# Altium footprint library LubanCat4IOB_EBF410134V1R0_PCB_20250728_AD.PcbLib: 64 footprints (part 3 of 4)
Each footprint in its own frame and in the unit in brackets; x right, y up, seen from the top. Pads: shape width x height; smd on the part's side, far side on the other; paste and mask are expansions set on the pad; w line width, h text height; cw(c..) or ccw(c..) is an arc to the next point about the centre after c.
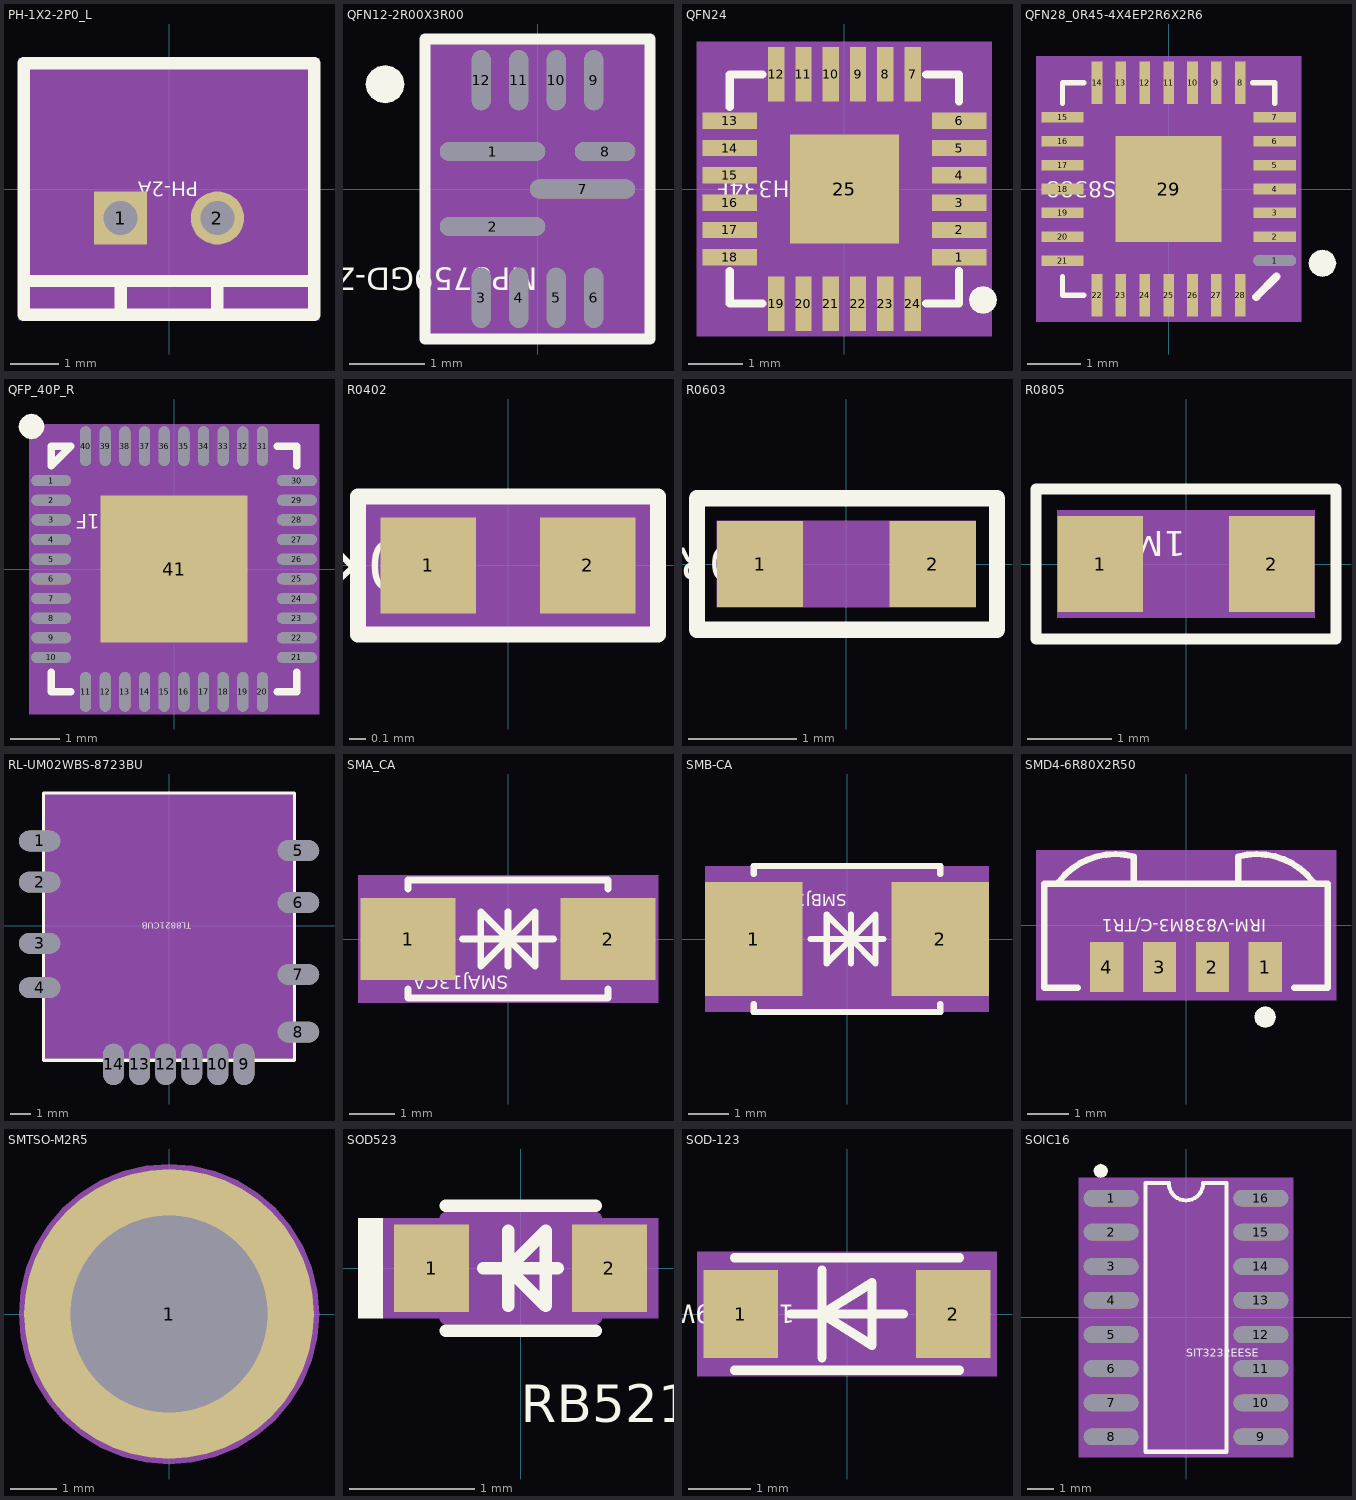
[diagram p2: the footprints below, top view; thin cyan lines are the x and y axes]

## PH-1X2-2P0_L [mm] "PH-1X2-2P0_L"
pads (2):
  rect 1.1x1.1 / inner round 1.524 / far side rect 1.1x1.1 hole 0.7: 1(-1,-0.6)
  round 1.1 / inner round 1.524 / far side round 1.1 hole 0.7: 2(1,-0.6)
Top Overlay:
  lines w0.254: -3,-1.9 3,-1.9 ; -1,-2.6 -1,-1.9 ; 1,-2.6 1,-1.9 ; -3,-2.6 -3,2.6 3,2.6 3,-2.6 -3,-2.6
  text "PH-2A" at 0.6,0.15 h0.3
Bottom Overlay:
  lines w0.6: 0,-1.1 0,-0.1
Top 3D Body:
  region: -3.1,2.7 -3.1,-2.7 3.1,-2.7 3.1,2.7
Mechanical 17:
  text "1" at -0.746,-0.6 h0.64
  text "2" at 1.254,-0.6 h0.64
Top Assembly:
  lines w0.025: -3.1,-2.7 -3.1,2.7 3.1,2.7 3.1,-2.7 -3.1,-2.7
3D body: height 3.81, standoff 0, extent -3.1,-2.7 3.1,2.7

## QFN12-2R00X3R00 [mm] "QFN12-2R00X3R00"
pads (12):
  oval 1.4x0.25 smd: 1(-0.6,0.5) 2(-0.6,-0.5) 7(0.6,0)
  oval 0.25x0.8 smd: 3(-0.75,-1.45) 4(-0.25,-1.45) 5(0.25,-1.45) 6(0.75,-1.45) 9(0.75,1.45) 10(0.25,1.45) 11(-0.25,1.45) 12(-0.75,1.45)
  oval 0.8x0.25 smd: 8(0.9,0.5)
Top Overlay:
  dashed: -2.032,1.652 -2.13,1.632 -2.212,1.577 -2.267,1.495 -2.287,1.397 -2.267,1.299 -2.249,1.272 -2.212,1.217 -2.13,1.162 -2.032,1.142 -1.934,1.162 -1.852,1.217 -1.815,1.272 -1.797,1.299 -1.777,1.397 -1.797,1.495 -1.852,1.577 -1.934,1.632
  lines w0.15: -1.5,-2 1.5,-2 1.5,2 1,2 -1.5,2 -1.5,-2
  text "MP8759GD-Z" at 0,-1.05 h0.3
Top 3D Body:
  region: -1.5,2 -1.5,-2 1.5,-2 1.5,2
Mechanical 17:
  text "12" at -0.75,1.37 h0.1
  text "6" at 0.75,-1.49 h0.1
  text "3" at -0.75,-1.49 h0.1
  text "8" at 0.9,0.46 h0.1
  text "7" at 0.6,-0.04 h0.1
  text "11" at -0.25,1.37 h0.1
  text "9" at 0.75,1.41 h0.1
  text "1" at -0.6,0.46 h0.1
  text "4" at -0.25,-1.49 h0.1
  text "10" at 0.25,1.37 h0.1
  text "2" at -0.6,-0.54 h0.1
  text "5" at 0.25,-1.49 h0.1
Top Assembly:
  lines w0.15: -1,-1.5 1,-1.5 1,1.5 -1,1.5 -1,-1.5
3D body: height 3.81, standoff 0, extent -1.5,-2 1.5,2

## QFN24 [mm] "QFN24"
pads (25):
  rect 1x0.3 smd: 1(2.1,-1.25) 2(2.1,-0.75) 3(2.1,-0.25) 4(2.1,0.25) 5(2.1,0.75) 6(2.1,1.25) 13(-2.1,1.25) 14(-2.1,0.75) 15(-2.1,0.25) 16(-2.1,-0.25) 17(-2.1,-0.75) 18(-2.1,-1.25)
  rect 0.3x1 smd: 7(1.25,2.1) 8(0.75,2.1) 9(0.25,2.1) 10(-0.25,2.1) 11(-0.75,2.1) 12(-1.25,2.1) 19(-1.25,-2.1) 20(-0.75,-2.1) 21(-0.25,-2.1) 22(0.25,-2.1) 23(0.75,-2.1) 24(1.25,-2.1)
  rect 2x2 smd: 25(0,0)
Top Overlay:
  dashed: 2.795,-2.032 2.775,-2.13 2.72,-2.212 2.638,-2.267 2.54,-2.287 2.442,-2.267 2.415,-2.249 2.36,-2.212 2.305,-2.13 2.285,-2.032 2.305,-1.934 2.36,-1.852 2.415,-1.815 2.442,-1.797 2.54,-1.777 2.638,-1.797 2.72,-1.852 2.775,-1.934
  lines w0.15: -2.1,-1.5 -2.1,-2.1 -1.5,-2.1 ; -2.1,1.5 -2.1,2.1 -1.5,2.1 ; 1.5,-2.1 2.1,-2.1 2.1,-1.5 ; 1.5,2.1 2.1,2.1 2.1,1.6
  text "CH334F" at -0.72,0.15 h0.3
Top 3D Body:
  region: 2.7,2.7 -2.7,2.7 -2.7,-2.7 2.7,-2.7
Mechanical 17:
  text "22" at -0.055,-2.1 h0.38
  text "23" at 0.445,-2.1 h0.38
  text "13" at -2.405,1.25 h0.38
  text "21" at -0.555,-2.1 h0.38
  text "2" at 1.948,-0.75 h0.38
  text "17" at -2.405,-0.75 h0.38
  text "24" at 0.945,-2.1 h0.38
  text "19" at -1.555,-2.1 h0.38
  text "11" at -1.055,2.1 h0.38
  text "14" at -2.405,0.75 h0.38
  text "9" at 0.098,2.1 h0.38
  text "15" at -2.405,0.25 h0.38
  text "7" at 1.098,2.1 h0.38
  text "5" at 1.948,0.75 h0.38
  text "16" at -2.405,-0.25 h0.38
  text "3" at 1.948,-0.25 h0.38
  text "20" at -1.055,-2.1 h0.38
  text "1" at 1.948,-1.25 h0.38
  text "4" at 1.948,0.25 h0.38
  text "18" at -2.405,-1.25 h0.38
  text "6" at 1.948,1.25 h0.38
  text "8" at 0.598,2.1 h0.38
  text "10" at -0.555,2.1 h0.38
  text "12" at -1.555,2.1 h0.38
  text "25" at -0.305,0 h0.38
Top Assembly:
  lines w0.2: -2.05,-2.05 2.05,-2.05 2.05,2.05 -2.05,2.05 -2.05,-2.05
3D body: height 3.81, standoff 0, extent -2.7,-2.7 2.7,2.7

## QFN28_0R45-4X4EP2R6X2R6 [mm] "QFN28_0R45-4X4EP2R6X2R6"
pads (29):
  oval 0.8x0.2 smd: 1(2,-1.35)
  rect 0.8x0.2 smd: 2(2,-0.9) 3(2,-0.45) 4(2,0) 5(2,0.45) 6(2,0.9) 7(2,1.35) 15(-2,1.35) 16(-2,0.9) 17(-2,0.45) 18(-2,0) 19(-2,-0.45) 20(-2,-0.9) 21(-2,-1.35)
  rect 0.2x0.8 smd: 8(1.35,2) 9(0.9,2) 10(0.45,2) 11(0,2) 12(-0.45,2) 13(-0.9,2) 14(-1.35,2) 22(-1.35,-2) 23(-0.9,-2) 24(-0.45,-2) 25(0,-2) 26(0.45,-2) 27(0.9,-2) 28(1.35,-2)
  rect 2x2 smd: 29(0,0)
Top Overlay:
  dashed: 3.155,-1.4 3.135,-1.498 3.08,-1.58 2.998,-1.635 2.9,-1.655 2.802,-1.635 2.775,-1.617 2.72,-1.58 2.665,-1.498 2.645,-1.4 2.665,-1.302 2.72,-1.22 2.775,-1.183 2.802,-1.165 2.9,-1.145 2.998,-1.165 3.08,-1.22 3.135,-1.302
  lines w0.1: -2,-1.657 -2,-2 -1.6,-2 ; -2,1.615 -2,2 -1.6,2 ; 1.587,2 2,2 2,1.615
  lines w0.152: 1.651,-2.032 2.032,-1.651
  text "ES8388" at -0.72,0.15 h0.3
Top 3D Body:
  region: 2.5,-2.5 2.5,2.5 -2.5,2.5 -2.5,-2.5
Mechanical 17:
  text "14" at -1.43,2 h0.1
  text "15" at -2.08,1.35 h0.1
  text "11" at -0.08,2 h0.1
  text "12" at -0.53,2 h0.1
  text "1" at 1.96,-1.35 h0.1
  text "5" at 1.96,0.45 h0.1
  text "6" at 1.96,0.9 h0.1
  text "7" at 1.96,1.35 h0.1
  text "8" at 1.31,2 h0.1
  text "28" at 1.27,-2 h0.1
  text "27" at 0.82,-2 h0.1
  text "26" at 0.37,-2 h0.1
  text "3" at 1.96,-0.45 h0.1
  text "2" at 1.96,-0.9 h0.1
  text "10" at 0.37,2 h0.1
  text "19" at -2.08,-0.45 h0.1
  text "20" at -2.08,-0.9 h0.1
  text "21" at -2.08,-1.35 h0.1
  text "22" at -1.43,-2 h0.1
  text "23" at -0.98,-2 h0.1
  text "24" at -0.53,-2 h0.1
  text "16" at -2.08,0.9 h0.1
  text "17" at -2.08,0.45 h0.1
  text "13" at -0.98,2 h0.1
  text "18" at -2.08,0 h0.1
  text "29" at -0.08,0 h0.1
  text "4" at 1.96,0 h0.1
  text "25" at -0.08,-2 h0.1
  text "9" at 0.86,2 h0.1
Top Assembly:
  lines w0.15: -2,-2 -2,2 2,2 2,-2 -2,-2
3D body: height 3.81, standoff 0, extent -2.5,-2.5 2.5,2.5

## QFP_40P_R [mil] "QFP_40P_R"
pads (41):
  oval 31.5x8.66 smd: 1(-98.43,70.87) 2(-98.43,55.12) 3(-98.43,39.37) 4(-98.43,23.62) 5(-98.43,7.87) 6(-98.43,-7.87) 7(-98.43,-23.62) 8(-98.43,-39.37) 9(-98.43,-55.12) 10(-98.43,-70.87) 21(98.43,-70.87) 22(98.43,-55.12) 23(98.43,-39.37) 24(98.43,-23.62) 25(98.43,-7.87) 26(98.43,7.87) 27(98.43,23.62) 28(98.43,39.37) 29(98.43,55.12) 30(98.43,70.87)
  oval 8.66x31.5 smd: 11(-70.87,-98.43) 12(-55.12,-98.43) 13(-39.37,-98.43) 14(-23.62,-98.43) 15(-7.87,-98.43) 16(7.87,-98.43) 17(23.62,-98.43) 18(39.37,-98.43) 19(55.12,-98.43) 20(70.87,-98.43) 31(70.87,98.43) 32(55.12,98.43) 33(39.37,98.43) 34(23.62,98.43) 35(7.87,98.43) 36(-7.87,98.43) 37(-23.62,98.43) 38(-39.37,98.43) 39(-55.12,98.43) 40(-70.87,98.43)
  rect 118.11x118.11 smd: 41(0,0)
Top Overlay:
  dashed: -114.17,104.14 -118.01,104.9 -121.27,107.08 -123.44,110.33 -124.21,114.17 -123.44,118.01 -122.72,119.1 -121.27,121.27 -118.01,123.44 -114.17,124.21 -110.33,123.44 -107.08,121.27 -105.63,119.1 -104.9,118.01 -104.14,114.17 -104.9,110.33 -107.08,107.08 -110.33,104.9
  lines w5.91: -98.43,-82.68 -98.43,-98.43 -82.68,-98.43 ; 82.68,-98.43 98.43,-98.43 98.43,-82.68 ; 82.68,98.43 98.43,98.43 98.43,82.68 ; -98.43,82.68 -98.43,98.43 -82.68,98.43 -98.43,82.68
  text "RTL8211F" at -0.01,43.7 h11.81
Top 3D Body:
  region: -116.14,-116.14 -116.14,116.14 116.14,116.14 116.14,-116.14
Mechanical 17:
  text "14" at -18.7,-89.57 h9.84
  text "13" at -34.45,-89.57 h9.84
  text "20" at 75.79,-89.57 h9.84
  text "19" at 60.04,-89.57 h9.84
  text "15" at -2.95,-89.57 h9.84
  text "16" at 12.79,-89.57 h9.84
  text "17" at 28.54,-89.57 h9.84
  text "18" at 44.29,-89.57 h9.84
  text "40" at -65.95,107.28 h9.84
  text "29" at 98.43,57.09 h9.84
  text "28" at 98.43,41.34 h9.84
  text "11" at -65.95,-89.57 h9.84
  text "26" at 98.43,9.84 h9.84
  text "27" at 98.43,25.59 h9.84
  text "22" at 98.43,-53.15 h9.84
  text "23" at 98.43,-37.4 h9.84
  text "24" at 98.43,-21.65 h9.84
  text "39" at -50.2,107.28 h9.84
  text "25" at 98.43,-5.9 h9.84
  text "35" at 12.79,107.28 h9.84
  text "34" at 28.54,107.28 h9.84
  text "33" at 44.29,107.28 h9.84
  text "32" at 60.04,107.28 h9.84
  text "12" at -50.2,-89.57 h9.84
  text "37" at -18.7,107.28 h9.84
  text "36" at -2.95,107.28 h9.84
  text "31" at 75.79,107.28 h9.84
  text "30" at 98.43,72.84 h9.84
  text "10" at -98.43,-66.94 h9.84
  text "9" at -98.43,-55.12 h9.84
  text "7" at -98.43,-23.62 h9.84
  text "6" at -98.43,-7.87 h9.84
  text "5" at -98.43,7.87 h9.84
  text "4" at -98.43,23.62 h9.84
  text "2" at -98.43,55.12 h9.84
  text "1" at -98.43,70.87 h9.84
  text "38" at -34.45,107.28 h9.84
  text "8" at -98.43,-39.37 h9.84
  text "3" at -98.43,39.37 h9.84
  text "21" at 98.43,-68.9 h9.84
  text "41" at 0,6 h20
Top Assembly:
  lines w1: -98.43,-98.43 -98.43,98.43 98.43,98.43 98.43,-98.43 -98.43,-98.43
3D body: height 150, standoff 0, extent -116.14,-116.14 116.14,116.14

## R0402 [mm] "R0402"
pads (2):
  rect 0.599x0.599 smd: 1(-0.5,0) 2(0.5,0)
Top Overlay:
  lines w0.102: -0.94,-0.432 0.94,-0.432 0.94,0.432 -0.94,0.432 -0.94,-0.432
  text "10K" at -0.36,0.15 h0.3
Top 3D Body:
  region: 0.94,0.432 0.94,-0.432 -0.94,-0.432 -0.94,0.432
Mechanical 17:
  text "1" at -0.754,0 h0.64
  text "2" at 0.246,0 h0.64
Top Assembly:
  dashed: -0.94,-0.432 -0.94,0.432 0.94,0.432 0.94,-0.432
3D body: height 3.81, standoff 0, extent -0.94,-0.432 0.94,0.432

## R0603 [mil] "R0603"
pads (2):
  rect 31.5x31.5 smd: 1(-31.5,0) 2(31.5,0)
Top Overlay:
  lines w6: -54.5,-24 55,-24 55,24 -54.5,24 -54.5,-24
  text "120R" at -18.9,5.91 h11.81
Top 3D Body:
  region: -47.24,-15.75 -47.24,15.75 47.24,15.75 47.24,-15.75
Mechanical 17:
  text "2" at 13.5,0 h45
  text "1" at -49.5,0 h45
3D body: height 150, standoff 0, extent -47.24,-15.75 47.24,15.75

## R0805 [mil] "R0805"
pads (2):
  rect 40x45 smd: 1(-40,0) 2(40,0)
Top Overlay:
  lines w5: -70,-35 70,-35 70,35 -70,35 -70,-35
  text "1M" at -0.01,15.35 h11.81
Top 3D Body:
  region: -60,25 60,25 60,-25 -60,-25
Mechanical 17:
  text "1" at -40,12 h30
  text "2" at 40,12 h30
3D body: height 150, standoff 0, extent -60,-25 60,25

## RL-UM02WBS-8723BU [mm] "RL-UM02WBS-8723BU"
pads (14):
  oval 2x1 smd: 1(-6.3,4.122) 2(-6.3,2.122) 3(-6.3,-0.858) 4(-6.3,-3.018) 5(6.3,3.652) 6(6.3,1.122) 7(6.3,-2.378) 8(6.3,-5.178)
  oval 1x2 smd: 9(3.65,-6.748) 10(2.38,-6.748) 11(1.11,-6.748) 12(-0.16,-6.748) 13(-1.43,-6.748) 14(-2.7,-6.748)
Top Overlay:
  lines w0.15: -6.1,-6.548 6.1,-6.548 6.1,6.452 -6.1,6.452 -6.1,-6.548
  text "TL8821CUB" at 1.08,0.15 h0.3
Top 3D Body:
  region: -6.096,-6.452 6.096,-6.452 6.096,6.452 -6.096,6.452
Mechanical 17:
  text "11" at 1.618,-6.748 h0.64
  text "14" at -2.192,-6.748 h0.64
  text "13" at -0.922,-6.748 h0.64
  text "12" at 0.348,-6.748 h0.64
  text "3" at -6.046,-0.858 h0.64
  text "9" at 3.904,-6.748 h0.64
  text "10" at 2.888,-6.748 h0.64
  text "4" at -6.046,-3.018 h0.64
  text "6" at 6.554,1.122 h0.64
  text "7" at 6.554,-2.378 h0.64
  text "2" at -6.046,2.122 h0.64
  text "8" at 6.554,-5.178 h0.64
  text "5" at 6.554,3.652 h0.64
  text "1" at -6.046,4.122 h0.64
3D body: height 3.81, standoff 0, extent -6.096,-6.452 6.096,6.452

## SMA_CA [mm] "SMA_CA"
pads (2):
  rect 2.1x1.8 smd: 1(-2.2,0) 2(2.2,0)
Top Overlay:
  lines w0.15: -2.2,-1.1 -2.2,-1.3 2.2,-1.3 2.2,-1.1 ; -2.2,1.1 -2.2,1.3 2.2,1.3 2.2,1.1 ; -1,0 1,0 ; 0,-0.6 0,0.6 ; 0,0 -0.6,-0.6 -0.6,0.6 0,0 ; 0,0 0.6,0.6 0.6,-0.6 0,0
  text "SMAJ13CA" at 0,-0.81 h0.3
Top 3D Body:
  region: -3.3,1.4 -3.3,-1.4 3.3,-1.4 3.3,1.4
Mechanical 17:
  text "2" at 2.2,-0.254 h0.64
  text "1" at -2.2,-0.254 h0.64
Top Assembly:
  lines w0.15: -2.2,-1.25 2.2,-1.25 2.2,1.25 -2.2,1.25 -2.2,-1.25
3D body: height 3.81, standoff 0, extent -3.3,-1.4 3.3,1.4

## SMB-CA [mm] "SMB-CA"
pads (2):
  rect 2.4x2.8 smd: 1(-2.3,0) 2(2.3,0)
Top Overlay:
  lines w0.15: -2.3,-1.6 -2.3,-1.8 2.3,-1.8 2.3,-1.6 ; -2.3,1.6 -2.3,1.8 2.3,1.8 2.3,1.6 ; -0.9,0 0.9,0 ; 0.1,0 0.7,0.6 0.7,-0.6 0.1,0 ; 0.1,0 -0.5,-0.6 -0.5,0.6 0.1,0 ; 0.1,-0.6 0.1,0.6 0.1,-0.6
  text "SMBJ15CA" at 0,1.11 h0.3
Top 3D Body:
  region: -3.5,1.8 -3.5,-1.8 3.5,-1.8 3.5,1.8
Mechanical 17:
  text "2" at 2.3,0.254 h0.64
  text "1" at -2.3,0.254 h0.64
Top Assembly:
  lines w0.15: -2.3,-1.8 2.3,-1.8 2.3,1.8 -2.3,1.8 -2.3,-1.8
3D body: height 3.81, standoff 0, extent -3.5,-1.8 3.5,1.8

## SMD4-6R80X2R50 [mm] "SMD4-6R80X2R50"
pads (4):
  rect 0.8x1.2 smd: 1(1.905,-1) 2(0.635,-1) 3(-0.635,-1) 4(-1.905,-1)
Top Overlay:
  dashed: 1.645,-2.2 1.664,-2.298 1.72,-2.38 1.802,-2.436 1.9,-2.455 1.998,-2.436 2.025,-2.417 2.08,-2.38 2.136,-2.298 2.155,-2.2 2.136,-2.102 2.08,-2.02 2.025,-1.983 1.998,-1.964 1.9,-1.945 1.802,-1.964 1.72,-2.02 1.664,-2.102
  lines w0.15: -2.6,-1.5 -3.4,-1.5 -3.4,1 3.4,1 3.4,-1.5 2.6,-1.5
  lines w0.152: -3.053,1.041 cw(c-1.7,0.011) -1.25,1.651 -1.25,1 ; 1.25,1 1.25,1.651 cw(c1.7,0.012) 3.053,1.041
  text "IRM-V838M3-C/TR1" at 1.92,0.15 h0.3
Top 3D Body:
  region: -3.6,1.8 -3.6,-1.8 3.6,-1.8 3.6,1.8
Mechanical 17:
  text "3" at -0.381,-1 h0.64
  text "2" at 0.889,-1 h0.64
  text "1" at 2.159,-1 h0.64
  text "4" at -1.651,-1 h0.64
Top Assembly:
  lines w0.15: -3.4,-1.5 3.4,-1.5 3.4,1 -3.4,1 -3.4,-1.5
3D body: height 3.81, standoff 0, extent -3.6,-1.8 3.6,1.8

## SMTSO-M2R5 [mm] "SMTSO-M2R5"
pads (1):
  round 6.2 / inner round 5.2 / far side round 5.2 hole 4.22: 1(0,0)
Top Overlay:
  text "M2.5X3mm" at -0.96,-0.15 h0.3
Top Paste:
  dashed: -0.4,3.074 -0.4,2.072 -0.579,2.029 -0.754,1.971 -0.923,1.898 -1.084,1.81 -1.238,1.709 -1.382,1.594 -1.516,1.468 -1.638,1.33 -1.748,1.182 -1.844,1.025 -1.926,0.861 -1.994,0.689 -2.047,0.513 -2.072,0.4 -3.074,0.4 -3.028,0.666 -2.958,0.928 -2.866,1.182 -2.752,1.427 -2.617,1.662 -2.462,1.883 -2.289,2.091 -2.098,2.282 -1.891,2.457 -1.67,2.612 -1.436,2.748 -1.191,2.862 -0.937,2.955 -0.676,3.026 -0.409,3.073
  dashed: -3.074,-0.4 -2.072,-0.4 -2.029,-0.579 -1.971,-0.754 -1.898,-0.923 -1.81,-1.084 -1.709,-1.238 -1.594,-1.382 -1.468,-1.516 -1.33,-1.638 -1.182,-1.748 -1.025,-1.844 -0.861,-1.926 -0.689,-1.994 -0.513,-2.047 -0.4,-2.072 -0.4,-3.074 -0.666,-3.028 -0.928,-2.958 -1.182,-2.866 -1.427,-2.752 -1.662,-2.617 -1.883,-2.462 -2.091,-2.289 -2.282,-2.098 -2.457,-1.891 -2.612,-1.67 -2.748,-1.436 -2.862,-1.191 -2.955,-0.937 -3.026,-0.676 -3.073,-0.409
  dashed: 0.4,-3.074 0.4,-2.072 0.579,-2.029 0.754,-1.971 0.923,-1.898 1.084,-1.81 1.238,-1.709 1.382,-1.594 1.516,-1.468 1.638,-1.33 1.748,-1.182 1.844,-1.025 1.926,-0.861 1.994,-0.689 2.047,-0.513 2.072,-0.4 3.074,-0.4 3.028,-0.666 2.958,-0.928 2.866,-1.182 2.752,-1.427 2.617,-1.662 2.462,-1.883 2.289,-2.091 2.098,-2.282 1.891,-2.457 1.67,-2.612 1.436,-2.748 1.191,-2.862 0.937,-2.955 0.676,-3.026 0.409,-3.073
  dashed: 3.074,0.4 2.072,0.4 2.029,0.579 1.971,0.754 1.898,0.923 1.81,1.084 1.709,1.238 1.594,1.382 1.468,1.516 1.33,1.638 1.182,1.748 1.025,1.844 0.861,1.926 0.689,1.994 0.513,2.047 0.4,2.072 0.4,3.074 0.666,3.028 0.928,2.958 1.182,2.866 1.427,2.752 1.662,2.617 1.883,2.462 2.091,2.289 2.282,2.098 2.457,1.891 2.612,1.67 2.748,1.436 2.862,1.191 2.955,0.937 3.026,0.676 3.073,0.409
Top 3D Body:
  region: 3.21,0 3.17,0.502 3.053,0.992 2.86,1.457 2.597,1.887 2.27,2.27 1.887,2.597 1.457,2.86 0.992,3.053 0.502,3.17 0,3.21 -0.502,3.17 -0.992,3.053 -1.457,2.86 -1.601,2.772 -1.887,2.597 -2.27,2.27 -2.597,1.887 -2.86,1.457 -3.053,0.992 -3.17,0.502 -3.21,0 -3.17,-0.502 -3.053,-0.992 -2.86,-1.457 -2.597,-1.887 -2.27,-2.27 -1.887,-2.597 -1.601,-2.772 -1.457,-2.86 -0.992,-3.053 -0.502,-3.17 0,-3.21 0.502,-3.17 0.992,-3.053 1.457,-2.86 1.887,-2.597 2.27,-2.27 2.597,-1.887 2.86,-1.457 3.053,-0.992 3.17,-0.502
Mechanical 17:
  text "1" at -0.254,0 h0.64
Top Assembly:
  circle w0.025: c0,0 r3.1
3D body: height 3.81, standoff 0, extent -3.21,-3.21 3.21,3.21

## SOD523 [mm] "SOD523"
pads (2):
  rect 0.6x0.7 smd: 1(-0.71,0) 2(0.71,0)
Top Overlay:
  dashed: -1.3,0.4 -1.3,-0.4 -1.1,-0.4 -1.1,0.4
  lines w0.1: -0.6,-0.5 0.6,-0.5 ; -0.6,0.5 0.6,0.5 ; -0.3,0 0.3,0 ; -0.1,-0.3 -0.1,0.3 ; -0.1,0 0.2,0.3 0.2,-0.3 -0.1,0
  text "RB521S-30" at 0,-1.23 h0.3
Top 3D Body:
  region: -1.1,0.4 -1.1,-0.4 1.1,-0.4 1.1,0.4
Mechanical 17:
  text "2" at 0.71,-0.254 h0.64
  text "1" at -0.71,-0.254 h0.64
Top Assembly:
  lines w0.1: -0.6,-0.4 0.6,-0.4 0.6,0.4 -0.6,0.4 -0.6,-0.4
3D body: height 3.81, standoff 0, extent -1.1,-0.4 1.1,0.4

## SOD-123 [mm] "SOD-123"
pads (2):
  rect 1.2x1.4 smd: 1(-1.7,0) 2(1.7,0)
Top Overlay:
  lines w0.15: -1.8,-0.9 1.8,-0.9 ; -1.8,0.9 1.8,0.9 ; -0.9,0 0.9,0 ; -0.4,-0.7 -0.4,0.7 ; -0.4,0 0.4,-0.5 0.4,0.5 -0.4,0
  text "1N5819W" at -0.84,0.15 h0.3
Top 3D Body:
  region: 2.4,1 -2.4,1 -2.4,-1 2.4,-1
Mechanical 17:
  text "1" at -2.015,0 h0.79
  text "2" at 1.385,0 h0.79
Top Assembly:
  lines w0.15: -1.8,-0.9 -1.8,0.9 1.8,0.9 1.8,-0.9 -1.8,-0.9
3D body: height 3.81, standoff 0, extent -2.4,-1 2.4,1

## SOIC16 [mil] "SOIC16"
pads (16):
  oval 80x24 smd: 1(-109.8,174.8) 2(-109.8,125.2) 3(-109.8,74.8) 4(-109.8,25.2) 5(-109.8,-25.2) 6(-109.8,-74.8) 7(-109.8,-125.2) 8(-109.8,-174.8) 9(109.8,-174.8) 10(109.8,-125.2) 11(109.8,-74.8) 12(109.8,-25.2) 13(109.8,25.2) 14(109.8,74.8) 15(109.8,125.2) 16(109.8,174.8)
Top Overlay:
  dashed: -125,225.04 -121.16,224.27 -117.9,222.1 -115.73,218.84 -114.96,215 -115.73,211.16 -116.46,210.07 -117.9,207.9 -121.16,205.73 -125,204.97 -128.84,205.73 -132.1,207.9 -133.54,210.07 -134.27,211.16 -135.03,215 -134.27,218.84 -132.1,222.1 -128.84,224.27
  lines w5.91: -59.05,-196.85 -59.05,196.85 -39.37,196.85 -25.2,196.85 ccw(c0,196.85) 25.2,196.85 59.05,196.85 59.05,-196.85 -59.05,-196.85
  text "SIT3232EESE" at 0.01,-57.87 h11.81
Top 3D Body:
  region: -157.48,204.72 -157.48,-204.72 157.48,-204.72 157.48,204.72
Mechanical 17:
  text "11" at 109.8,-84.24 h11.8
  text "12" at 109.8,-34.64 h11.8
  text "10" at 109.8,-134.64 h11.8
  text "9" at 109.8,-179.52 h11.8
  text "2" at -109.8,120.48 h11.8
  text "6" at -109.8,-79.52 h11.8
  text "5" at -109.8,-29.92 h11.8
  text "4" at -109.8,20.48 h11.8
  text "3" at -109.8,70.08 h11.8
  text "1" at -109.8,170.08 h11.8
  text "16" at 109.8,165.36 h11.8
  text "7" at -109.8,-129.92 h11.8
  text "14" at 109.8,65.36 h11.8
  text "13" at 109.8,15.76 h11.8
  text "8" at -109.8,-179.52 h11.8
  text "15" at 109.8,115.76 h11.8
3D body: height 150, standoff 0, extent -157.48,-204.72 157.48,204.72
